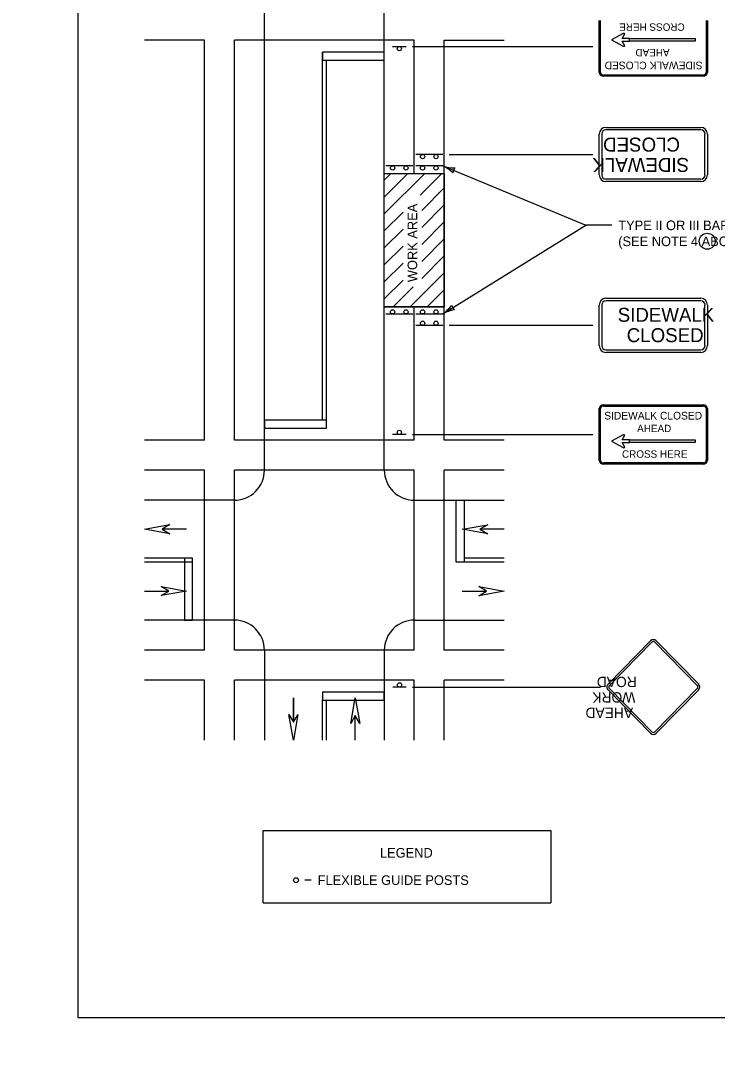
# Model space of a CAD drawing. Extents: x 49991.4 to 50021, y 49987.6 to 50011.4.
# Drawn here: x 49999.98 to 50004.33, y 49999.86 to 50006.3 of the extents above; entities that cross this region are included whole.
import ezdxf

# ---------------------------------------------------------------- set-up
doc = ezdxf.new("R2010")
doc.units = 0
for name, color, linetype in [('Level 1', 7, 'Continuous'), ('Level 2', 7, 'Continuous'), ('Level 3', 7, 'Continuous')]:
    doc.layers.add(name, color=color, linetype=linetype)

msp = doc.modelspace()

# ---------------------------------------------------------------- linework, layer by layer
at = {"layer": 'Level 1'}
for p, q in [((50001.501, 50003.4852), (50001.501, 50006.3628)), ((50002.251, 50003.4852), (50002.251, 50006.3628)), ((50003.5945, 50005.9728), (50003.5945, 50006.2979)), ((50003.6033, 50005.9728), (50003.6033, 50006.2979)), ((50004.263, 50006.2979), (50004.263, 50005.9728)), ((50004.2719, 50006.2979), (50004.2719, 50005.9728)), ((50003.7452, 50006.217), (50003.6722, 50006.1773)), ((50003.7387, 50006.1855), (50003.7539, 50006.2146)), ((50001.126, 50006.1753), (50000.751, 50006.1753)), ((50001.126, 50003.6727), (50001.126, 50006.1753)), ((50001.3135, 50003.6727), (50001.3135, 50006.1753)), ((50002.4385, 50006.1753), (50001.3135, 50006.1753)), ((50002.4385, 50005.3895), (50002.4385, 50006.1753)), ((50002.626, 50003.6727), (50002.626, 50006.1753)), ((50002.626, 50006.1753), (50003.001, 50006.1753)), ((50003.6722, 50006.1773), (50003.7452, 50006.1376)), ((50003.7848, 50006.1855), (50003.7387, 50006.1855)), ((50003.7539, 50006.14), (50003.7387, 50006.1691)), ((50003.7387, 50006.1691), (50003.7848, 50006.1691)), ((50003.7848, 50006.1691), (50003.7848, 50006.1855)), ((50001.8635, 50003.7977), (50001.8635, 50006.1003)), ((50002.3028, 50006.1353), (50002.3866, 50006.1353)), ((50001.8885, 50003.7977), (50001.8885, 50006.0503)), ((50004.2436, 50005.9574), (50003.6227, 50005.9574)), ((50004.2436, 50005.9503), (50003.6227, 50005.9503)), ((50003.5945, 50005.3334), (50003.5945, 50005.5875)), ((50003.6104, 50005.5875), (50003.6104, 50005.3334)), ((50003.6368, 50005.6298), (50004.2296, 50005.6298)), ((50004.2296, 50005.6139), (50003.6368, 50005.6139)), ((50004.256, 50005.3334), (50004.256, 50005.5875)), ((50004.2719, 50005.5875), (50004.2719, 50005.3334)), ((50002.5322, 50005.4604), (50002.4485, 50005.4604)), ((50002.616, 50005.4604), (50002.5322, 50005.4604)), ((50002.3447, 50005.3895), (50002.261, 50005.3895)), ((50002.4285, 50005.3895), (50002.3447, 50005.3895)), ((50002.4385, 50005.3411), (50002.4385, 50005.3895)), ((50002.5322, 50005.3895), (50002.4485, 50005.3895)), ((50002.616, 50005.3895), (50002.5322, 50005.3895)), ((50002.251, 50005.3411), (50002.626, 50005.3411)), ((50002.251, 50005.3003), (50002.2918, 50005.3411)), ((50002.251, 50005.1942), (50002.3979, 50005.3411)), ((50002.251, 50005.0881), (50002.504, 50005.3411)), ((50002.4748, 50005.2059), (50002.61, 50005.3411)), ((50002.4846, 50005.1097), (50002.626, 50005.251)), ((50003.6368, 50005.307), (50004.2296, 50005.307)), ((50004.2296, 50005.2911), (50003.6368, 50005.2911)), ((50002.4846, 50005.0036), (50002.626, 50005.1449)), ((50002.251, 50004.9821), (50002.3681, 50005.0992)), ((50002.251, 50004.876), (50002.3681, 50004.9931)), ((50002.4846, 50004.8975), (50002.626, 50005.0389)), ((50002.4846, 50004.7915), (50002.626, 50004.9328)), ((50002.251, 50004.7699), (50002.3681, 50004.887)), ((50002.4846, 50004.6854), (50002.626, 50004.8267)), ((50002.251, 50004.6639), (50002.3681, 50004.781)), ((50002.251, 50004.5578), (50002.3681, 50004.6749)), ((50002.4122, 50004.5069), (50002.626, 50004.7207)), ((50002.3062, 50004.5069), (50002.4318, 50004.6325)), ((50002.5183, 50004.5069), (50002.626, 50004.6146)), ((50003.6368, 50004.5611), (50004.2296, 50004.5611)), ((50004.2296, 50004.5452), (50003.6368, 50004.5452)), ((50002.251, 50004.5069), (50002.626, 50004.5069)), ((50002.4385, 50003.6727), (50002.4385, 50004.5069)), ((50002.4385, 50004.4627), (50002.4385, 50004.5069)), ((50002.6244, 50004.5069), (50002.626, 50004.5085)), ((50003.5945, 50004.2648), (50003.5945, 50004.5188)), ((50003.6104, 50004.5188), (50003.6104, 50004.2648)), ((50004.256, 50004.2648), (50004.256, 50004.5188)), ((50004.2719, 50004.5188), (50004.2719, 50004.2648)), ((50002.261, 50004.4627), (50002.3447, 50004.4627)), ((50002.3447, 50004.4627), (50002.4285, 50004.4627)), ((50002.4485, 50004.4627), (50002.5322, 50004.4627)), ((50002.5322, 50004.4627), (50002.616, 50004.4627)), ((50002.4485, 50004.3918), (50002.5322, 50004.3918)), ((50002.5322, 50004.3918), (50002.616, 50004.3918)), ((50003.6368, 50004.2383), (50004.2296, 50004.2383)), ((50004.2296, 50004.2224), (50003.6368, 50004.2224)), ((50003.5945, 50003.546), (50003.5945, 50003.8711)), ((50003.6033, 50003.546), (50003.6033, 50003.8711)), ((50003.6227, 50003.8935), (50004.2436, 50003.8935)), ((50003.6227, 50003.8865), (50004.2436, 50003.8865)), ((50004.263, 50003.8711), (50004.263, 50003.546)), ((50004.2719, 50003.8711), (50004.2719, 50003.546)), ((50002.3866, 50003.7085), (50002.3028, 50003.7085)), ((50003.7452, 50003.7063), (50003.6722, 50003.6666)), ((50001.126, 50003.6727), (50000.751, 50003.6727)), ((50002.4385, 50003.6727), (50001.3135, 50003.6727)), ((50003.001, 50003.6727), (50002.626, 50003.6727)), ((50003.6722, 50003.6666), (50003.7452, 50003.6269)), ((50003.7387, 50003.6748), (50003.7539, 50003.7039)), ((50003.7848, 50003.6748), (50003.7387, 50003.6748)), ((50003.7539, 50003.6293), (50003.7387, 50003.6584)), ((50003.7387, 50003.6584), (50003.7848, 50003.6584)), ((50003.7848, 50003.6584), (50003.7848, 50003.6748)), ((50004.2436, 50003.5306), (50003.6227, 50003.5306)), ((50004.2436, 50003.5236), (50003.6227, 50003.5236)), ((50004.1712, 50003.5236), (50004.1712, 50003.5236)), ((50001.126, 50003.4852), (50000.751, 50003.4852)), ((50001.126, 50002.3602), (50001.126, 50003.4852)), ((50002.4385, 50003.4852), (50001.3135, 50003.4852)), ((50001.3135, 50002.3602), (50001.3135, 50003.4852)), ((50002.4385, 50002.3602), (50002.4385, 50003.4852)), ((50002.626, 50002.3602), (50002.626, 50003.4852)), ((50003.001, 50003.4852), (50002.626, 50003.4852)), ((50001.3135, 50003.2977), (50000.751, 50003.2977)), ((50002.4385, 50003.2977), (50003.001, 50003.2977)), ((50001.0143, 50003.1168), (50000.8618, 50003.1168)), ((50001.0143, 50003.1165), (50000.8618, 50003.1165)), ((50003.001, 50003.1166), (50002.8485, 50003.1166)), ((50003.001, 50003.1165), (50002.8485, 50003.1165)), ((50001.051, 50002.9352), (50000.751, 50002.9352)), ((50003.001, 50002.9352), (50002.751, 50002.9352)), ((50001.051, 50002.9102), (50000.751, 50002.9102)), ((50003.001, 50002.9102), (50002.751, 50002.9102)), ((50000.751, 50002.729), (50000.9035, 50002.729)), ((50000.751, 50002.7289), (50000.9035, 50002.7289)), ((50002.7377, 50002.729), (50002.8901, 50002.729)), ((50002.7377, 50002.7287), (50002.8901, 50002.7287)), ((50001.3135, 50002.5477), (50000.751, 50002.5477)), ((50002.4385, 50002.5477), (50003.001, 50002.5477)), ((50003.6498, 50002.1471), (50003.915, 50002.4178)), ((50003.9513, 50002.4178), (50004.2165, 50002.1471)), ((50001.126, 50002.3602), (50000.751, 50002.3602)), ((50002.4385, 50002.3602), (50001.3135, 50002.3602)), ((50001.501, 50002.3602), (50001.501, 50001.7977)), ((50002.251, 50002.3602), (50002.251, 50001.7977)), ((50003.001, 50002.3602), (50002.626, 50002.3602)), ((50003.6587, 50002.1384), (50003.9239, 50002.4091)), ((50003.9425, 50002.4091), (50004.2077, 50002.1384)), ((50001.126, 50002.1727), (50000.751, 50002.1727)), ((50001.126, 50001.7977), (50001.126, 50002.1727)), ((50002.4385, 50002.1727), (50001.3135, 50002.1727)), ((50001.3135, 50001.7977), (50001.3135, 50002.1727)), ((50002.4385, 50001.7977), (50002.4385, 50002.1727)), ((50002.626, 50001.7977), (50002.626, 50002.1727)), ((50003.001, 50002.1727), (50002.626, 50002.1727)), ((50002.388, 50002.129), (50002.3043, 50002.129)), ((50003.915, 50001.8402), (50003.6498, 50002.1109)), ((50003.9239, 50001.8489), (50003.6587, 50002.1196)), ((50004.2077, 50002.1196), (50003.9425, 50001.8489)), ((50004.2165, 50002.1109), (50003.9513, 50001.8402)), ((50001.6818, 50002.0611), (50001.6818, 50001.9086)), ((50001.6821, 50002.0611), (50001.6821, 50001.9086)), ((50001.8635, 50001.7977), (50001.8635, 50002.0477)), ((50001.8885, 50001.7977), (50001.8885, 50002.0477)), ((50002.0696, 50001.7977), (50002.0696, 50001.9502)), ((50002.0697, 50001.7977), (50002.0697, 50001.9502)), ((49999.9766, 49999.8624), (49999.9766, 49999.8624))]:
    msp.add_line(p, q, dxfattribs=at)
for points in [[(50008.6146, 50011.2628), (50000.3356, 50011.2628), (50000.3356, 50000.0624), (50008.6146, 50000.0624)], [(50001.8635, 50006.1003), (50001.8635, 50006.0503), (50002.251, 50006.0503), (50002.251, 50006.1003)], [(50002.251, 50005.3411), (50002.626, 50005.3411), (50002.626, 50004.5069), (50002.251, 50004.5069)], [(50001.8885, 50003.7477), (50001.8885, 50003.7977), (50001.501, 50003.7977), (50001.501, 50003.7477)], [(50002.751, 50002.9102), (50002.701, 50002.9102), (50002.701, 50003.2977), (50002.751, 50003.2977)], [(50000.9106, 50003.0884), (50000.751, 50003.1165), (50000.9106, 50003.1448), (50000.8619, 50003.1165)], [(50002.8973, 50003.0883), (50002.7377, 50003.1165), (50002.8973, 50003.1447), (50002.8486, 50003.1165)], [(50001.051, 50002.9352), (50001.001, 50002.9352), (50001.001, 50002.5477), (50001.051, 50002.5477)], [(50000.8547, 50002.7572), (50001.0143, 50002.729), (50000.8547, 50002.7008), (50000.9034, 50002.729)], [(50002.8413, 50002.7571), (50003.001, 50002.729), (50002.8413, 50002.7006), (50002.8901, 50002.729)], [(50001.8635, 50002.0977), (50001.8635, 50002.0477), (50002.251, 50002.0477), (50002.251, 50002.0977)], [(50002.0414, 50001.9014), (50002.0696, 50002.0611), (50002.0978, 50001.9014), (50002.0696, 50001.9502)], [(50001.7102, 50001.9574), (50001.6821, 50001.7977), (50001.6537, 50001.9574), (50001.6821, 50001.9086)]]:
    msp.add_lwpolyline(points, close=True, dxfattribs=at)
for points in [[(50003.7848, 50006.1855), (50004.1942, 50006.1855), (50004.1942, 50006.1691), (50003.7848, 50006.1691), (50003.7848, 50006.1855)], [(50004.1942, 50003.6584), (50003.7848, 50003.6584), (50003.7848, 50003.6748), (50004.1942, 50003.6748), (50004.1942, 50003.6584)]]:
    msp.add_lwpolyline(points, dxfattribs=at)
for centre, radius in [((50002.3448, 50006.1221), 0.0133), ((50002.4904, 50005.4472), 0.0133), ((50002.5741, 50005.4472), 0.0133), ((50002.3028, 50005.3763), 0.0133), ((50002.3866, 50005.3763), 0.0133), ((50002.4904, 50005.3763), 0.0133), ((50002.5741, 50005.3763), 0.0133), ((50002.3028, 50004.476), 0.0133), ((50002.3866, 50004.476), 0.0133), ((50002.4904, 50004.476), 0.0133), ((50002.5741, 50004.476), 0.0133), ((50002.4904, 50004.405), 0.0133), ((50002.5741, 50004.405), 0.0133), ((50002.3447, 50003.7218), 0.0133), ((50002.3461, 50002.1422), 0.0133), ((50001.6991, 50000.9213), 0.015)]:
    msp.add_circle(centre, radius, dxfattribs=at)
for centre, radius, start, end in [((50003.6368, 50005.5875), 0.0423, 90, 180), ((50003.6368, 50005.5875), 0.0265, 90, 180), ((50004.2296, 50005.5875), 0.0423, 360, 90), ((50004.2296, 50005.5875), 0.0265, 360, 90), ((50003.6368, 50005.3334), 0.0423, 180, 270), ((50003.6368, 50005.3334), 0.0265, 180, 270), ((50004.2296, 50005.3334), 0.0423, 270, 360), ((50004.2296, 50005.3334), 0.0265, 270, 360), ((50003.6368, 50004.5188), 0.0423, 90, 180), ((50003.6368, 50004.5188), 0.0265, 90, 180), ((50004.2296, 50004.5188), 0.0423, 360, 90), ((50004.2296, 50004.5188), 0.0265, 360, 90), ((50003.6368, 50004.2648), 0.0423, 180, 270), ((50003.6368, 50004.2648), 0.0265, 180, 270), ((50004.2296, 50004.2648), 0.0423, 270, 360), ((50004.2296, 50004.2648), 0.0265, 270, 360), ((50001.3135, 50003.4852), 0.1875, 270, 0), ((50002.4385, 50003.4852), 0.1875, 180, 270), ((50001.3135, 50002.3602), 0.1875, 0, 90), ((50002.4385, 50002.3602), 0.1875, 90, 180)]:
    msp.add_arc(centre, radius, start, end, dxfattribs=at)
for centre, major_axis, ratio, start_param, end_param in [((50003.749, 50006.2152), (0.00512, 0), 0.494321, 6.030588, 8.68654), ((50003.749, 50006.1393), (-0.00512, 0), 0.494321, 0.738238, 3.39419), ((50003.6227, 50005.9728), (0.0282, 0), 0.794444, 3.141593, 4.712389), ((50003.6227, 50005.9728), (0.0194, 0), 0.794444, 3.141593, 4.712389), ((50004.2436, 50005.9728), (0.0282, 0), 0.794444, 4.712389, 6.283185), ((50004.2436, 50005.9728), (0.0194, 0), 0.794444, 4.712389, 6.283185), ((50003.6227, 50003.8711), (-0.0282, 0), 0.794444, 4.712389, 6.283185), ((50003.6227, 50003.8711), (-0.0194, 0), 0.794444, 4.712389, 6.283185), ((50004.2436, 50003.8711), (-0.0282, 0), 0.794444, 3.141593, 4.712389), ((50004.2436, 50003.8711), (-0.0194, 0), 0.794444, 3.141593, 4.712389), ((50003.749, 50003.7046), (0.00512, 0), 0.494321, 6.030588, 8.68654), ((50003.749, 50003.6286), (-0.00512, 0), 0.494321, 0.738238, 3.39419), ((50003.6227, 50003.546), (-0.0282, 0), 0.794444, 0, 1.570796), ((50003.6227, 50003.546), (-0.0194, 0), 0.794444, 0, 1.570796), ((50004.2436, 50003.546), (0.0282, 0), 0.794444, 4.712389, 6.283185), ((50004.2436, 50003.546), (0.0194, 0), 0.794444, 4.712389, 6.283185), ((50003.9332, 50002.3996), (0, 0.0258), 0.98963, 5.497787, 7.068583), ((50003.9332, 50002.3996), (0, 0.0134), 0.98, 5.497787, 7.068583), ((50003.6679, 50002.129), (0, 0.0258), 0.98963, 0.785394, 2.356194), ((50003.6679, 50002.129), (0, 0.0134), 0.98, 0.785394, 2.356194), ((50004.1984, 50002.129), (0, 0.0134), 0.98, 3.926991, 5.497787), ((50004.1984, 50002.129), (0, 0.0258), 0.98963, 3.926991, 5.497787), ((50003.9332, 50001.8583), (0, -0.0258), 0.98963, 5.497795, 7.068583), ((50003.9332, 50001.8583), (0, -0.0134), 0.98, 5.497795, 7.068583)]:
    msp.add_ellipse(centre, major_axis=major_axis, ratio=ratio, start_param=start_param, end_param=end_param, dxfattribs=at)
at = {"layer": 'Level 2'}
for p, q in [((50001.4926, 50000.7786), (50001.4926, 50001.2322)), ((50001.4926, 50001.2322), (50003.2923, 50001.2322)), ((50003.2923, 50001.2322), (50003.2923, 50000.7786)), ((50001.7941, 50000.9213), (50001.7541, 50000.9213)), ((50001.4926, 50000.7786), (50003.2923, 50000.7786))]:
    msp.add_line(p, q, dxfattribs=at)
msp.add_circle((50004.2699, 50004.9179), 0.0501, dxfattribs=at)
at = {"layer": 'Level 3'}
for p, q in [((50002.4266, 50006.1353), (50003.5545, 50006.1353)), ((50002.656, 50005.4604), (50003.5545, 50005.4604)), ((50002.616, 50005.3895), (50003.5119, 50005.018)), ((50002.616, 50004.4627), (50003.5119, 50005.018)), ((50003.6736, 50005.018), (50003.5119, 50005.018)), ((50002.656, 50004.3918), (50003.5545, 50004.3918)), ((50002.4266, 50003.7085), (50003.5545, 50003.7085)), ((50002.428, 50002.129), (50003.6024, 50002.129))]:
    msp.add_line(p, q, dxfattribs=at)
for centre, radius, start, end in [((50002.5224, 50005.1879), 0.2223, 44.93191, 65.11542), ((50002.6945, 50005.6089), 0.233, 250.30321, 269.55306), ((50002.7344, 50005.3404), 0.0548, 139.61472, 175.33708), ((50002.4836, 50004.6545), 0.233, 304.61726, 323.86711), ((50002.7252, 50004.2691), 0.2223, 99.24596, 119.42947), ((50002.725, 50004.5303), 0.0548, 193.92877, 229.65113)]:
    msp.add_arc(centre, radius, start, end, dxfattribs=at)

# ---------------------------------------------------------------- texts
at = {"layer": 'Level 1'}
for s, height, rotation, p in [('CROSS HERE', 0.04633, 180, (50004.1293, 50006.2804)), ('AHEAD', 0.04632, 180, (50004.0344, 50006.1205)), ('SIDEWALK CLOSED', 0.047878, 180, (50004.2404, 50006.0413)), ('CLOSED', 0.08743, 180, (50004.0998, 50005.5659)), ('SIDEWALK', 0.08743, 180, (50004.1563, 50005.4386)), ('SIDEWALK', 0.08743, 360, (50003.7101, 50004.4136)), ('CLOSED', 0.08743, 360, (50003.7666, 50004.2864)), ('ROAD', 0.06453, 180, (50003.829, 50002.1935)), ('WORK', 0.06453, 180, (50003.8199, 50002.0967)), ('AHEAD', 0.06453, 180, (50003.8062, 50002))]:
    msp.add_text(s, height=height, rotation=rotation, dxfattribs=at).set_placement(p)
for s, height, p in [('SIDEWALK CLOSED', 0.047878, (50003.6259, 50003.8026)), ('AHEAD', 0.04632, (50003.8319, 50003.7234)), ('CROSS HERE', 0.04633, (50003.737, 50003.5634))]:
    msp.add_text(s, height=height, dxfattribs=at).set_placement(p)
at = {"layer": 'Level 2'}
msp.add_text('WORK AREA', height=0.06, rotation=90, dxfattribs=at).set_placement((50002.4564, 50004.6617))
for s, p in [('TYPE II OR III BARRICADES', (50003.7136, 50004.9871)), ('(SEE NOTE 4 ABOVE)', (50003.7136, 50004.8871)), ('LEGEND', (50002.2238, 50001.0622)), ('FLEXIBLE GUIDE POSTS', (50001.8341, 50000.8913))]:
    msp.add_text(s, height=0.06, dxfattribs=at).set_placement(p)

doc.saveas('drawing.dxf')
